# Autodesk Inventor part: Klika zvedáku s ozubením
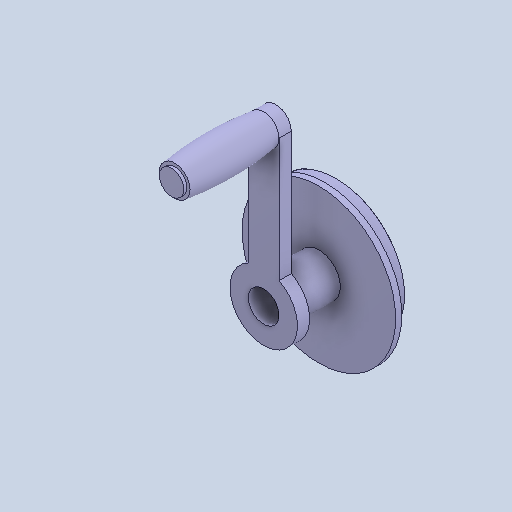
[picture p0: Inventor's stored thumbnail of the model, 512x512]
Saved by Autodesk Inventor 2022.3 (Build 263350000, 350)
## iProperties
Created: 2022-03
Part Number: Klika zvedáku s ozubením
Material: Všeobecné
Document SubType Name: Modeling
Designer: Hra42
Density: 1 g/cm^3
Appearance: Výchozí
Author: Hra42
Sending System: SolidWorks 2012
Last Author: Hra42
Last Saved: 2025-11-13
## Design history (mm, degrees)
feature "Importovaný1"
node "Těleso1"
